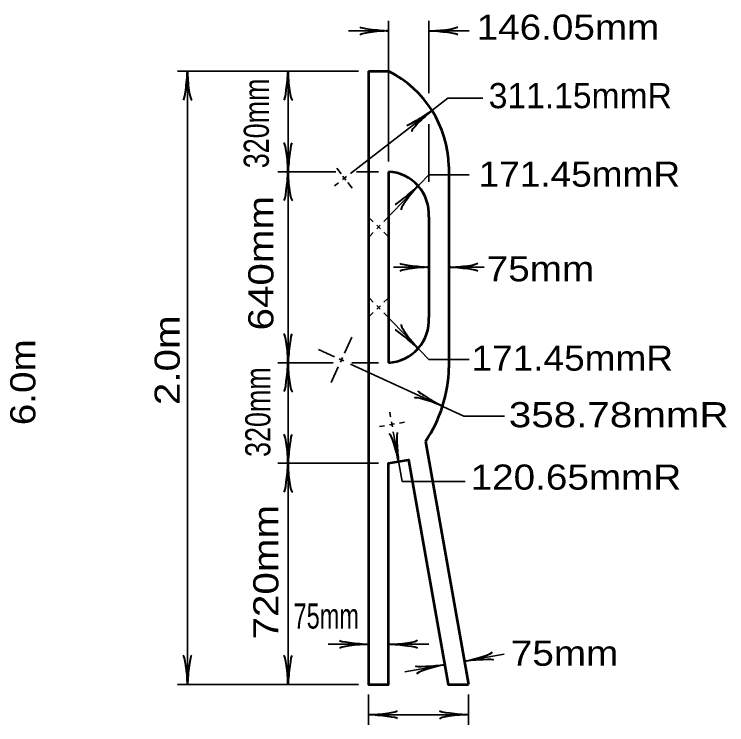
# Model space of a CAD drawing. Extents: x -96 to 617, y -65 to 388.
# Drawn here: x 37.5 to 108.4, y 126.4 to 197 of the extents above; entities that cross this region are included whole.
import ezdxf

# ---------------------------------------------------------------- set-up
doc = ezdxf.new("R2010")
doc.units = 0
doc.layers.add('1', color=7, linetype='Continuous', lineweight=53)

msp = doc.modelspace()

# ---------------------------------------------------------------- linework, layer by layer
at = {"layer": '1', "lineweight": 35}
for p, q in [((74.754, 182.362), (74.754, 196.362)), ((78.754, 189.181), (78.754, 196.362)), ((74.754, 195.362), (70.754, 195.362)), ((78.754, 195.362), (82.754, 195.362)), ((71.754, 191.362), (53.754, 191.362)), ((54.754, 191.362), (54.754, 130.362)), ((64.754, 181.362), (64.754, 191.362)), ((80.65, 188.663), (70.954, 181.181)), ((80.65, 188.663), (84.135, 188.663)), ((78.754, 180.362), (78.754, 186.088)), ((69.493, 181.362), (63.754, 181.362)), ((69.596, 181.712), (70.022, 181.16)), ((73.754, 181.362), (71.547, 181.362)), ((70.558, 180.876), (70.162, 180.57)), ((70.207, 180.921), (70.513, 180.525)), ((78.754, 181.048), (74.274, 176.402)), ((78.754, 181.048), (82.766, 181.048)), ((69.766, 180.265), (69.371, 179.959)), ((71.124, 179.733), (70.704, 180.277)), ((72.854, 176.73), (73.214, 176.383)), ((73.574, 176.036), (73.934, 175.689)), ((73.927, 176.042), (73.58, 175.682)), ((73.233, 175.322), (72.886, 174.962)), ((74.294, 175.341), (74.653, 174.994)), ((78.754, 171.862), (75.254, 171.862)), ((80.754, 171.862), (84.254, 171.862)), ((73.233, 168.402), (72.886, 168.762)), ((74.294, 168.383), (74.653, 168.73)), ((73.574, 167.689), (73.934, 168.036)), ((73.927, 167.682), (73.58, 168.042)), ((72.854, 166.994), (73.214, 167.342)), ((78.754, 162.676), (74.274, 167.322)), ((71.097, 164.889), (70.379, 163.325)), ((69.385, 162.956), (67.794, 163.686)), ((69.238, 162.362), (63.754, 162.362)), ((70.294, 162.539), (69.839, 162.748)), ((70.171, 162.871), (69.962, 162.416)), ((82.247, 157.055), (70.975, 162.227)), ((73.754, 162.362), (71.102, 162.362)), ((78.754, 162.676), (82.766, 162.676)), ((69.754, 161.962), (69.04, 160.408)), ((74.87, 157.46), (74.957, 156.968)), ((82.247, 157.055), (86.259, 157.055)), ((73.856, 156.012), (74.349, 156.099)), ((75.334, 156.272), (74.841, 156.185)), ((75.044, 156.475), (75.131, 155.983)), ((75.826, 156.359), (76.318, 156.446)), ((75.218, 155.49), (75.305, 154.998)), ((75.304, 154.998), (76.086, 150.566)), ((73.754, 152.362), (63.754, 152.362)), ((64.754, 152.362), (64.754, 130.362)), ((76.086, 150.566), (82.349, 150.566)), ((72.754, 134.362), (68.754, 134.362)), ((74.754, 134.362), (78.754, 134.362)), ((86.226, 133.373), (82.286, 132.678)), ((80.317, 132.331), (76.377, 131.636)), ((71.754, 130.362), (53.754, 130.362)), ((72.754, 129.362), (72.754, 126.362)), ((82.695, 129.362), (82.695, 126.362)), ((72.754, 127.362), (82.695, 127.362))]:
    msp.add_line(p, q, dxfattribs=at)
at = {"layer": '1'}
for p, q in [((72.754, 191.362), (74.754, 191.362)), ((74.754, 181.362), (74.754, 162.362)), ((80.754, 181.862), (80.754, 161.862)), ((78.754, 176.862), (78.754, 166.862)), ((78.432, 154.534), (82.695, 130.362))]:
    msp.add_line(p, q, dxfattribs=at)
msp.add_lwpolyline([(72.754, 191.362), (72.754, 130.362), (74.754, 130.362), (74.754, 152.362), (76.723, 152.71), (80.664, 130.362), (82.695, 130.362)], dxfattribs=at)
at = {"layer": '1', "lineweight": 35}
msp.add_lwpolyline([(64.754, 181.362), (64.754, 162.362), (64.754, 152.362)], dxfattribs=at)
at = {"layer": '1'}
for centre, radius, start, end in [((69.819, 181.601), 10.938, 1.37066, 63.18064), ((74.51, 177.118), 4.251, 356.54913, 86.71796), ((74.51, 166.606), 4.251, 273.28204, 3.45087), ((67.036, 162.176), 13.721, 326.15622, 358.69102)]:
    msp.add_arc(centre, radius, start, end, dxfattribs=at)
at = {"layer": '1', "lineweight": 40}
for centre, major_axis, ratio, start_param, end_param in [((73.633, 195.574), (1.756, -0.176), 0.07063, 3.140715, 5.41811), ((73.633, 195.574), (1.756, -0.176), 0.07063, 3.140715, 5.41811), ((79.845, 195.639), (-1.786, -0.156), 0.122415, 0.896353, 3.141593), ((79.845, 195.639), (-1.786, -0.156), 0.122415, 0.896353, 3.141593), ((73.663, 195.086), (1.786, 0.156), 0.122415, 0.896353, 3.141593), ((73.663, 195.086), (1.786, 0.156), 0.122415, 0.896353, 3.141593), ((79.874, 195.151), (-1.756, 0.176), 0.07063, 3.140715, 5.41811), ((79.874, 195.151), (-1.756, 0.176), 0.07063, 3.140715, 5.41811), ((54.542, 190.242), (0.176, 1.756), 0.07063, 3.140715, 5.41811), ((54.542, 190.242), (0.176, 1.756), 0.07063, 3.140715, 5.41811), ((55.03, 190.271), (-0.156, 1.786), 0.122415, 0.896353, 3.141593), ((55.03, 190.271), (-0.156, 1.786), 0.122415, 0.896353, 3.141593), ((64.542, 190.242), (0.176, 1.756), 0.07063, 3.140715, 5.41811), ((64.542, 190.242), (0.176, 1.756), 0.07063, 3.140715, 5.41811), ((65.03, 190.271), (-0.156, 1.786), 0.122415, 0.896353, 3.141593), ((65.03, 190.271), (-0.156, 1.786), 0.122415, 0.896353, 3.141593), ((78.05, 186.925), (1.498, 0.934), 0.07063, 3.140715, 5.41811), ((78.372, 186.556), (1.318, 1.215), 0.122415, 0.896353, 3.141593), ((64.477, 182.453), (0.156, -1.786), 0.122415, 0.896353, 3.141593), ((64.477, 182.453), (0.156, -1.786), 0.122415, 0.896353, 3.141593), ((64.965, 182.483), (-0.176, -1.756), 0.07063, 3.140715, 5.41811), ((64.965, 182.483), (-0.176, -1.756), 0.07063, 3.140715, 5.41811), ((64.542, 180.242), (0.176, 1.756), 0.07063, 3.140715, 5.41811), ((64.542, 180.242), (0.176, 1.756), 0.07063, 3.140715, 5.41811), ((65.03, 180.271), (-0.156, 1.786), 0.122415, 0.896353, 3.141593), ((65.03, 180.271), (-0.156, 1.786), 0.122415, 0.896353, 3.141593), ((76.758, 179.283), (-1.346, -1.143), 0.07063, 6.282307, 8.559703), ((76.758, 179.283), (-1.346, -1.143), 0.07063, 6.282307, 8.559703), ((77.129, 178.965), (1.127, 1.394), 0.122415, 0.896353, 3.141593), ((77.129, 178.965), (1.127, 1.394), 0.122415, 0.896353, 3.141593), ((77.633, 172.074), (1.756, -0.176), 0.07063, 3.140715, 5.41811), ((77.633, 172.074), (1.756, -0.176), 0.07063, 3.140715, 5.41811), ((81.845, 172.139), (-1.786, -0.156), 0.122415, 0.896353, 3.141593), ((77.663, 171.586), (1.786, 0.156), 0.122415, 0.896353, 3.141593), ((77.663, 171.586), (1.786, 0.156), 0.122415, 0.896353, 3.141593), ((81.874, 171.651), (-1.756, 0.176), 0.07063, 3.140715, 5.41811), ((77.129, 164.759), (1.127, -1.394), 0.122415, 3.141593, 5.386832), ((64.477, 163.453), (0.156, -1.786), 0.122415, 0.896353, 3.141593), ((64.477, 163.453), (0.156, -1.786), 0.122415, 0.896353, 3.141593), ((64.965, 163.483), (-0.176, -1.756), 0.07063, 3.140715, 5.41811), ((64.965, 163.483), (-0.176, -1.756), 0.07063, 3.140715, 5.41811), ((76.758, 164.442), (-1.346, 1.143), 0.07063, 4.006668, 6.284063), ((64.542, 161.242), (0.176, 1.756), 0.07063, 3.140715, 5.41811), ((64.542, 161.242), (0.176, 1.756), 0.07063, 3.140715, 5.41811), ((65.03, 161.271), (-0.156, 1.786), 0.122415, 0.896353, 3.141593), ((65.03, 161.271), (-0.156, 1.786), 0.122415, 0.896353, 3.141593), ((79.187, 158.692), (1.523, -0.892), 0.07063, 3.140715, 5.41811), ((79.01, 158.236), (1.688, -0.603), 0.122415, 0.896353, 3.141593), ((64.477, 153.453), (0.156, -1.786), 0.122415, 0.896353, 3.141593), ((64.477, 153.453), (0.156, -1.786), 0.122415, 0.896353, 3.141593), ((64.965, 153.483), (-0.176, -1.756), 0.07063, 3.140715, 5.41811), ((64.965, 153.483), (-0.176, -1.756), 0.07063, 3.140715, 5.41811), ((75.277, 153.563), (0.464, -1.731), 0.122415, 0.896353, 3.141593), ((75.752, 153.676), (0.132, -1.76), 0.07063, 3.140715, 5.41811), ((64.542, 151.242), (0.176, 1.756), 0.07063, 3.140715, 5.41811), ((64.542, 151.242), (0.176, 1.756), 0.07063, 3.140715, 5.41811), ((65.03, 151.271), (-0.156, 1.786), 0.122415, 0.896353, 3.141593), ((65.03, 151.271), (-0.156, 1.786), 0.122415, 0.896353, 3.141593), ((71.633, 134.574), (1.756, -0.176), 0.07063, 3.140715, 5.41811), ((75.845, 134.639), (-1.786, -0.156), 0.122415, 0.896353, 3.141593), ((71.663, 134.086), (1.786, 0.156), 0.122415, 0.896353, 3.141593), ((75.874, 134.151), (-1.756, 0.176), 0.07063, 3.140715, 5.41811), ((54.477, 131.453), (0.156, -1.786), 0.122415, 0.896353, 3.141593), ((54.477, 131.453), (0.156, -1.786), 0.122415, 0.896353, 3.141593), ((54.965, 131.483), (-0.176, -1.756), 0.07063, 3.140715, 5.41811), ((54.965, 131.483), (-0.176, -1.756), 0.07063, 3.140715, 5.41811), ((64.477, 131.453), (0.156, -1.786), 0.122415, 0.896353, 3.141593), ((64.965, 131.483), (-0.176, -1.756), 0.07063, 3.140715, 5.41811), ((83.313, 133.14), (-1.731, -0.464), 0.122415, 0.896353, 3.141593), ((83.426, 132.664), (-1.76, -0.132), 0.07063, 3.140715, 5.41811), ((79.176, 132.344), (-1.76, -0.132), 0.07063, 6.282307, 8.559703), ((79.29, 131.869), (1.731, 0.464), 0.122415, 0.896353, 3.141593), ((73.845, 127.639), (-1.786, -0.156), 0.122415, 0.896353, 3.141593), ((81.574, 127.574), (1.756, -0.176), 0.07063, 3.140715, 5.41811), ((73.874, 127.151), (-1.756, 0.176), 0.07063, 3.140715, 5.41811), ((81.603, 127.086), (1.786, 0.156), 0.122415, 0.896353, 3.141593)]:
    msp.add_ellipse(centre, major_axis=major_axis, ratio=ratio, start_param=start_param, end_param=end_param, dxfattribs=at)

# ---------------------------------------------------------------- texts
at = {"layer": '1'}
for s, width, p in [('146.05mm', 1.15, (83.504, 194.48)), ('171.45mmR', 1.1, (83.704, 179.867)), ('75mm', 1.15, (84.505, 170.459)), ('171.45mmR', 1.1, (82.998, 161.573)), ('358.78mmR', 1.2, (86.706, 155.946)), ('120.65mmR', 1.15, (82.904, 149.741)), ('75mm', 0.7, (65.303, 135.926)), ('75mm', 1.15, (86.906, 132.226))]:
    msp.add_text(s, height=2.5, dxfattribs=dict(at, width=width)).set_placement(p)
for s, width, p in [('320mm', 0.8, (62.849, 181.704)), ('640mm', 1.2, (63.302, 165.571)), ('2.0m', 1.2, (53.988, 158.148)), ('6.0m', 1.15, (39.636, 156.148)), ('320mm', 0.8, (62.997, 152.992)), ('720mm', 1.2, (63.798, 134.844))]:
    msp.add_text(s, height=2.5, rotation=90, dxfattribs=dict(at, width=width)).set_placement(p)
msp.add_text('311.15mmR', height=2.5, dxfattribs=at).set_placement((84.705, 187.674))

doc.saveas('drawing.dxf')
